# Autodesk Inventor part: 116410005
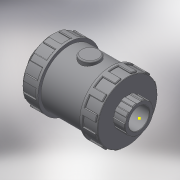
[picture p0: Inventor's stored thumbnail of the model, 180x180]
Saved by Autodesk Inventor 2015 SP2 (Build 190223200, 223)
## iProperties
Created: 2017-11
Part Number: 116410005
Material: Generic
Description: PLASSON FOOT VALVE THR PVC 1/2"
Document SubType Name: Modeling
Designer: KIM
Density: 1 g/cm^3
Appearance: Default
Author: KIM
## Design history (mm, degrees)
derived "116410 - 116010.ipt"
feature "Solid1::116410 - 116010.ipt"
tag "TaggingFeature1"
body "Solid1"
other parameters: "d0" = 75, "d1" = 18.631, "d2" = 45, "d3" = 15, "d4" = 14.9048, "d5" = 10.5, "d7" = 26.0834, "d8" = 40.5, "d13" = 0.55893, "d23" = 15, "d24" = 43.2, "d25" = 0.37262, "d26" = 0.55893, "d27" = 6.75, "d28" = 3.375, "d29" = 11.25, "d30" = 0, "d35" = 0.55893, "d39" = 22.5, "d45" = 360 deg, "d47" = 0.37262, "d50" = 22.5, "d51" = 13.5, "d53" = 0, "d54" = 0.9, "d55" = 3.7262, "d56" = 1.8631, "d58" = 0, "d59" = 0.55893, "d61" = 360 deg, "G_" = 18.631, "l_" = 15, "H_" = 75, "K_" = 45
